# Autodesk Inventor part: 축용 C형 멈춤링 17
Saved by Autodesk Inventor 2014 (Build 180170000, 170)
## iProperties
Created: 2026-05
Part Number: 축용 C형 멈춤링 17
Material: 일반
Document SubType Name: Modeling
Designer: dg
Density: 1 g/cm^3
Appearance: 기본값
Author: dg
Author: jhkim
Description: 리테이닝 링(C형)
Creation Date: 2026-04-27
Sending System: Autodesk Inventor 2027
Preprocessor: ST-DEVELOPER v20.1
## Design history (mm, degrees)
node "축용 C형 멈춤링 171"
body "Solid1"
node "기준1"
